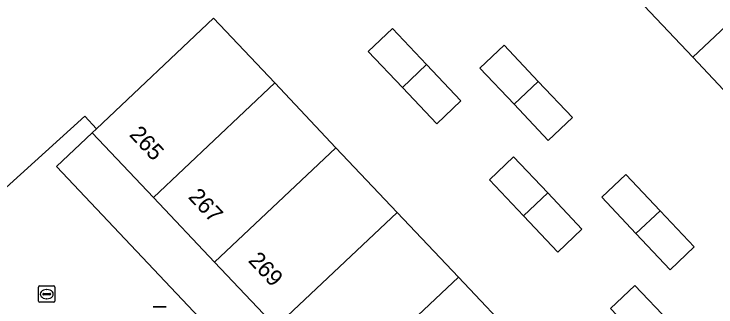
# Model space of a CAD drawing. Extents: x 162542 to 163147, y 380779 to 381521.
# Drawn here: x 162864.72 to 162907.61, y 381427.46 to 381445.37 of the extents above; entities that cross this region are included whole.
import ezdxf

# ---------------------------------------------------------------- set-up
doc = ezdxf.new("R2010")
doc.units = 0
for name, color, linetype in [('IMGEO_Erf', 7, 'Continuous'), ('IMGEO_Lichtmast', 7, 'Continuous'), ('IMGEO_Pand', 7, 'Continuous'), ('IMGEO_Pand_nummerreeks', 7, 'Continuous'), ('IMGEO_Rioolput', 7, 'Continuous'), ('IMGEO_Voetpad_open', 7, 'Continuous')]:
    doc.layers.add(name, color=color, linetype=linetype)

msp = doc.modelspace()

# ---------------------------------------------------------------- linework, layer by layer
at = {"layer": 'IMGEO_Erf'}
for points in [[(162909.933, 381438.77), (162906.197, 381442.726), (162902.462, 381446.682)], [(162861.159, 381432.002), (162869.05, 381439.12), (162869.767, 381438.361), (162876.917, 381445.114), (162880.655, 381441.156), (162884.393, 381437.198), (162888.132, 381433.24), (162891.87, 381429.282), (162895.608, 381425.324), (162899.346, 381421.365), (162903.084, 381417.407), (162906.823, 381413.449), (162908.963, 381415.47)]]:
    msp.add_lwpolyline(points, dxfattribs=at)
for points in [[(162886.36, 381443.089), (162887.839, 381444.482), (162889.932, 381442.278), (162892.024, 381440.074), (162890.549, 381438.665), (162888.455, 381440.876)], [(162893.183, 381442.062), (162894.661, 381443.471), (162896.756, 381441.253), (162898.849, 381439.036), (162897.361, 381437.64), (162895.272, 381439.851)], [(162888.193, 381418.32), (162884.455, 381422.279), (162880.718, 381426.238), (162876.98, 381430.196), (162873.243, 381434.155), (162869.505, 381438.114), (162867.324, 381436.054), (162904.333, 381396.849), (162906.52, 381398.909), (162903.143, 381402.486), (162899.406, 381406.444), (162895.668, 381410.403), (162891.93, 381414.362)], [(162895.244, 381436.634), (162897.335, 381434.429), (162899.426, 381432.225), (162897.942, 381430.811), (162895.854, 381433.024), (162893.769, 381435.234)], [(162902.114, 381435.565), (162904.202, 381433.347), (162906.285, 381431.133), (162904.811, 381429.731), (162902.72, 381431.949), (162900.628, 381434.167)], [(162902.654, 381428.781), (162904.744, 381426.573), (162906.833, 381424.364), (162905.354, 381422.952), (162903.258, 381425.167), (162901.17, 381427.375)]]:
    msp.add_lwpolyline(points, close=True, dxfattribs=at)
at = {"layer": 'IMGEO_Lichtmast'}
for p, q in [((162873.227, 381427.461), (162874.017, 381427.461)), ((162874.017, 381427.461), (162873.227, 381427.461))]:
    msp.add_line(p, q, dxfattribs=at)
at = {"layer": 'IMGEO_Pand'}
for points in [[(162913.649, 381449.762), (162909.918, 381453.723), (162902.462, 381446.682), (162906.197, 381442.726)], [(162917.379, 381445.801), (162913.649, 381449.762), (162906.197, 381442.726), (162909.933, 381438.77)], [(162880.655, 381441.156), (162876.917, 381445.114), (162869.767, 381438.361), (162869.505, 381438.114), (162873.243, 381434.155)], [(162887.839, 381444.482), (162886.36, 381443.089), (162888.455, 381440.876), (162889.932, 381442.278)], [(162893.183, 381442.062), (162895.272, 381439.851), (162896.756, 381441.253), (162894.661, 381443.471)], [(162889.932, 381442.278), (162888.455, 381440.876), (162890.549, 381438.665), (162892.024, 381440.074)], [(162884.393, 381437.198), (162880.655, 381441.156), (162873.243, 381434.155), (162876.98, 381430.196)], [(162896.756, 381441.253), (162895.272, 381439.851), (162897.361, 381437.64), (162898.849, 381439.036)], [(162888.132, 381433.24), (162884.393, 381437.198), (162876.98, 381430.196), (162880.718, 381426.238)], [(162895.244, 381436.634), (162893.769, 381435.234), (162895.854, 381433.024), (162897.335, 381434.429)], [(162900.628, 381434.167), (162902.72, 381431.949), (162904.202, 381433.347), (162902.114, 381435.565)], [(162897.335, 381434.429), (162895.854, 381433.024), (162897.942, 381430.811), (162899.426, 381432.225)], [(162891.87, 381429.282), (162888.132, 381433.24), (162880.718, 381426.238), (162884.455, 381422.279)], [(162904.202, 381433.347), (162902.72, 381431.949), (162904.811, 381429.731), (162906.285, 381431.133)], [(162895.608, 381425.324), (162891.87, 381429.282), (162884.455, 381422.279), (162888.193, 381418.32)], [(162902.654, 381428.781), (162901.17, 381427.375), (162903.258, 381425.167), (162904.744, 381426.573)]]:
    msp.add_lwpolyline(points, close=True, dxfattribs=at)
at = {"layer": 'IMGEO_Rioolput'}
for p, q in [((162866.219, 381427.821), (162866.219, 381428.673)), ((162866.294, 381428.747), (162867.146, 381428.747)), ((162867.22, 381428.673), (162867.22, 381427.821)), ((162866.478, 381428.241), (162866.478, 381428.253)), ((162866.521, 381428.29), (162866.919, 381428.29)), ((162866.707, 381428.527), (162866.732, 381428.527)), ((162866.962, 381428.253), (162866.962, 381428.241)), ((162866.916, 381428.204), (162866.518, 381428.204)), ((162866.73, 381427.967), (162866.705, 381427.967)), ((162867.146, 381427.747), (162866.294, 381427.747))]:
    msp.add_line(p, q, dxfattribs=at)
for points in [[(162866.219, 381427.821), (162866.219, 381428.673)], [(162866.294, 381428.747), (162867.146, 381428.747)], [(162867.22, 381428.673), (162867.22, 381427.821)], [(162867.146, 381427.747), (162866.294, 381427.747)]]:
    msp.add_lwpolyline(points, dxfattribs=at)
for centre, radius, start, end in [((162866.296, 381428.671), 0.0765, 91.552, 178.448), ((162866.296, 381428.671), 0.0765, 91.552, 178.448), ((162867.144, 381428.671), 0.0765, 1.552, 88.448), ((162867.144, 381428.671), 0.0765, 1.552, 88.448), ((162866.518, 381428.25), 0.0403, 85.8775, 175.7526), ((162866.515, 381428.24), 0.0366, 178.938, 274.7102), ((162866.919, 381428.247), 0.043, 264.8664, 352.4533), ((162866.923, 381428.252), 0.0386, 1.7309, 96.639), ((162866.296, 381427.823), 0.0765, 181.552, 268.448), ((162866.296, 381427.823), 0.0765, 181.552, 268.448), ((162867.144, 381427.823), 0.0765, 271.552, 358.448), ((162867.144, 381427.823), 0.0765, 271.552, 358.448)]:
    msp.add_arc(centre, radius, start, end, dxfattribs=at)
for centre, major_axis, ratio, start_param, end_param in [((162866.706, 381428.247), (-0.387, 0.002), 0.722429, 4.712389, 7.853982), ((162866.731, 381428.247), (-0.39, 0.002), 0.717154, 1.570796, 4.712389)]:
    msp.add_ellipse(centre, major_axis=major_axis, ratio=ratio, start_param=start_param, end_param=end_param, dxfattribs=at)
at = {"layer": 'IMGEO_Voetpad_open'}
msp.add_lwpolyline([(162911.974, 381388.738), (162908.153, 381392.793), (162904.333, 381396.849), (162867.324, 381436.054), (162869.505, 381438.114), (162869.767, 381438.361), (162869.05, 381439.12), (162861.159, 381432.002), (162859.586, 381433.676), (162859.038, 381433.161), (162858.949, 381433.255), (162856.034, 381430.516), (162856.123, 381430.422), (162855.576, 381429.908), (162857.637, 381427.714), (162849.743, 381420.296), (162845.564, 381416.369), (162841.367, 381412.426), (162837.186, 381408.498), (162833.031, 381404.902)], dxfattribs=at)

# ---------------------------------------------------------------- texts
at = {"layer": 'IMGEO_Pand_nummerreeks'}
for s, rotation, p in [('265', 313.155, (162871.718, 381437.962)), ('267', 313.1492, (162875.316, 381434.15)), ('269', 313.1664, (162878.988, 381430.26))]:
    msp.add_text(s, height=1, rotation=rotation, dxfattribs=at).set_placement(p)

doc.saveas('drawing.dxf')
